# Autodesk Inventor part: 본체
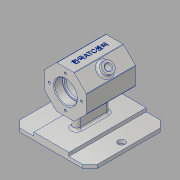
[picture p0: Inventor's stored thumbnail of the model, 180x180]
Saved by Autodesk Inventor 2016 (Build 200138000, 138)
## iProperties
Created: 2018-06
Part Number: 본체
Material: 알루미늄 6061
Document SubType Name: Modeling
Designer: 605-15
Mass: 552.644 g
Surface Area: 601.052 cm^2
Volume: 204.683 cm^3
Density: 2.7 g/cm^3
Appearance: 알루미늄 - 평지
Author: 605-15
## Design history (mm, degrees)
sketch "스케치1"
  geometry: L1 (-55, 5)-(55, 5); L2 (55, 5)-(55, 0); L3 (55, 0)-(-55, 0); L4 (-55, 0)-(-55, 5); L5 (-55, 5)-(55, 0); L6 (55, 5)-(-55, 0); L7 (25, 0)-(-25, 0); L8 (-25, 0)-(-25, 10); L9 (-25, 10)-(25, 10); L10 (25, 10)-(25, 0); 5 further points
  constraints: 20 end point, 5 midpoint, 4 parallel, 2 horizontal, 2 perpendicular, 2 vertical alignment, 1 coincident, 1 point on line
  dimensions: "d0" = 5 distance of L3.end L1.start; "d1" = 10 distance of L7.end L8.end; "d3" = 110 distance of L1.start L1.end; "d4" = 30 distance between parallel lines of L4 L8
extrude "돌출1" new body sketch "스케치1" stored distance "d5" = 110; taper "d6" = 0 deg
sketch "스케치2"
  geometry: L1 (20, 36)-(20, 74); L2 (30, 74)-(30, 36); A1 r 5 centre (25, 74) between (30, 74) and (20, 74); A2 r 5 centre (25, 36) between (20, 36) and (30, 36); 2 further points
  constraints: 4 end point, 4 point on circle, 4 tangent, 2 centre point, 2 vertical, 2 vertical alignment, 1 horizontal alignment, 1 midpoint
  dimensions: "d7" = 38 distance of L1.start L1.end; "d8" = 5 radius of A1
extrude "돌출2" join sketch "스케치2" distance "d9" = 60; taper "d10" = 0 deg
sketch "스케치3"
  geometry: L1 (-12.426, 92)-(12.426, 92); L2 (12.426, 92)-(30, 74.426); L3 (30, 74.426)-(30, 49.574); L4 (30, 49.574)-(12.426, 32); L5 (12.426, 32)-(-12.426, 32); L6 (-12.426, 32)-(-30, 49.574); L7 (-30, 49.574)-(-30, 74.426); L8 (-30, 74.426)-(-12.426, 92); C1 r 30 at (0, 62); 4 further points
  constraints: 16 end point, 6 tangent, 3 midpoint, 3 parallel, 2 vertical alignment, 1 centre point, 1 horizontal, 1 horizontal alignment, 1 perpendicular, 1 vertical
  dimensions: "d11" = 60 diameter of C1; "d12" = 62 distance of point (0, 0) C1.centre; "d13" = 45 deg dimension on C1.centre L1.end L1.start
extrude "돌출3" join sketch "스케치3" stored distance "d14" = 70; taper "d15" = 0 deg
sketch "스케치4"
  geometry: L1 (74.426, 35)-(49.574, 35) reference; L2 (92, 35)-(74.426, 35) reference; L3 (49.574, 35)-(32, 35) reference; L4 (49.574, -35)-(74.426, -35) reference; L5 (74.426, -35)-(92, -35) reference; L6 (32, -35)-(49.574, -35) reference; L7 (62, 35)-(62, -35); L8 (78, 35)-(78, 23); L9 (78, 23)-(76, 23); L10 (76, 23)-(76, 20); L11 (76, 20)-(87, 20); L12 (87, 20)-(87, -20); L13 (87, -20)-(76, -20); L14 (76, -20)-(76, -23); L15 (76, -23)-(78, -23); L16 (78, -23)-(78, -35); 1 further point
  constraints: 20 end point, 6 perpendicular, 6 point on line, 2 collinear, 2 midpoint, 1 vertical
  dimensions: "d16" = 12 distance of L8.start L8.end; "d17" = 3 distance of L9.end L10.end; "d18" = 32 diameter of L8 L7; "d19" = 28 diameter of L10 L7; "d20" = 50 diameter of L12 L7
revolve "회전1" sketch "스케치4" stored, may be unused: angle "d21" = 90 deg
sketch "스케치5"
  geometry: L1 (3.574, 0)-(-28.426, 0) reference; L2 (-28.426, 70)-(3.574, 70) reference; L3 (0, 70)-(17.574, 70) reference; L4 (17.574, 70)-(0, 70) reference; L5 (0, 70)-(-24.853, 70) reference; L6 (-24.853, 70)-(-42.426, 70) reference; L7 (-42.426, 70)-(-24.853, 70) reference; L8 (-24.853, 70)-(0, 70) reference; C1 r 8 at (-12.426, 35); 2 further points
  constraints: 1 centre point, 1 horizontal alignment, 1 midpoint, 1 vertical alignment
  dimensions: "d22" = 16 diameter of C1
extrude "돌출4" join sketch "스케치5" distance "d23" = 7; taper "d24" = 0 deg
hole "구멍1" diameter "d27" = 8; stored, may be unused: countersink angle "d31" = 90 deg, drill point angle "d33" = 118 deg; dims "d25" = 10, "d26" = 10, "d28" = 6, "d29" = 4, "d30" = 2, "d32" = 15
sketch "스케치6"
  geometry: C1 r 14 at (0, 62) reference; A1 r 23 centre (0, 62) between (0, 85) and (23, 62); 4 further points
  constraints: 4 point on circle, 2 horizontal alignment, 2 vertical alignment, 1 centre point, 1 coincident
  dimensions: "d35" = 46 diameter of A1
hole "구멍2" sketch "스케치6" at (0, 85), (23, 62), (-23, 62), (0, 39) diameter "d36" = 3.242; stored, may be unused: countersink angle "d40" = 90 deg, drill point angle "d42" = 118 deg; dims "d37" = 8, "d38" = 4, "d39" = 2, "d41" = 10
sketch "스케치7"
  geometry: L1 (-80, 110)-(-80, 0) reference; L2 (30, 110)-(30, 0) reference; C1 r 5 at (20, 55); C2 r 5 at (-70, 55); 1 further point
  constraints: 2 centre point, 2 horizontal alignment, 1 equal radius
  dimensions: "d43" = 10 diameter of C2; "d44" = 10 distance from line of L1 C2.centre; "d45" = 10 distance from line of L2 C1.centre
extrude "돌출5" cut sketch "스케치7" stored distance "d46" = 0; taper "d47" = 0 deg
chamfer "모따기1" distance "d48" = 10; stored, may be unused: second distance "d49" = 2, angle "d50" = 45 deg
sketch "스케치8"
  geometry: 2 further points
  constraints: 1 coincident, 1 other
feature "엠보싱1" sketch "스케치8" dims "d51" = 0.5, "d52" = 0
chamfer "모따기2" distance "d53" = 1; stored, may be unused: second distance "d54" = 2, angle "d55" = 45 deg
fillet "모깎기1" dims "d56" = 0.3
fillet "모깎기2" dims "d57" = 3
fillet "모깎기3" dims "d58" = 1
node "솔리드1"
mirror "대칭1"
node "투영된 루프1"
